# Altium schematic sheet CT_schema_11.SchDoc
size 210 x 185 mm
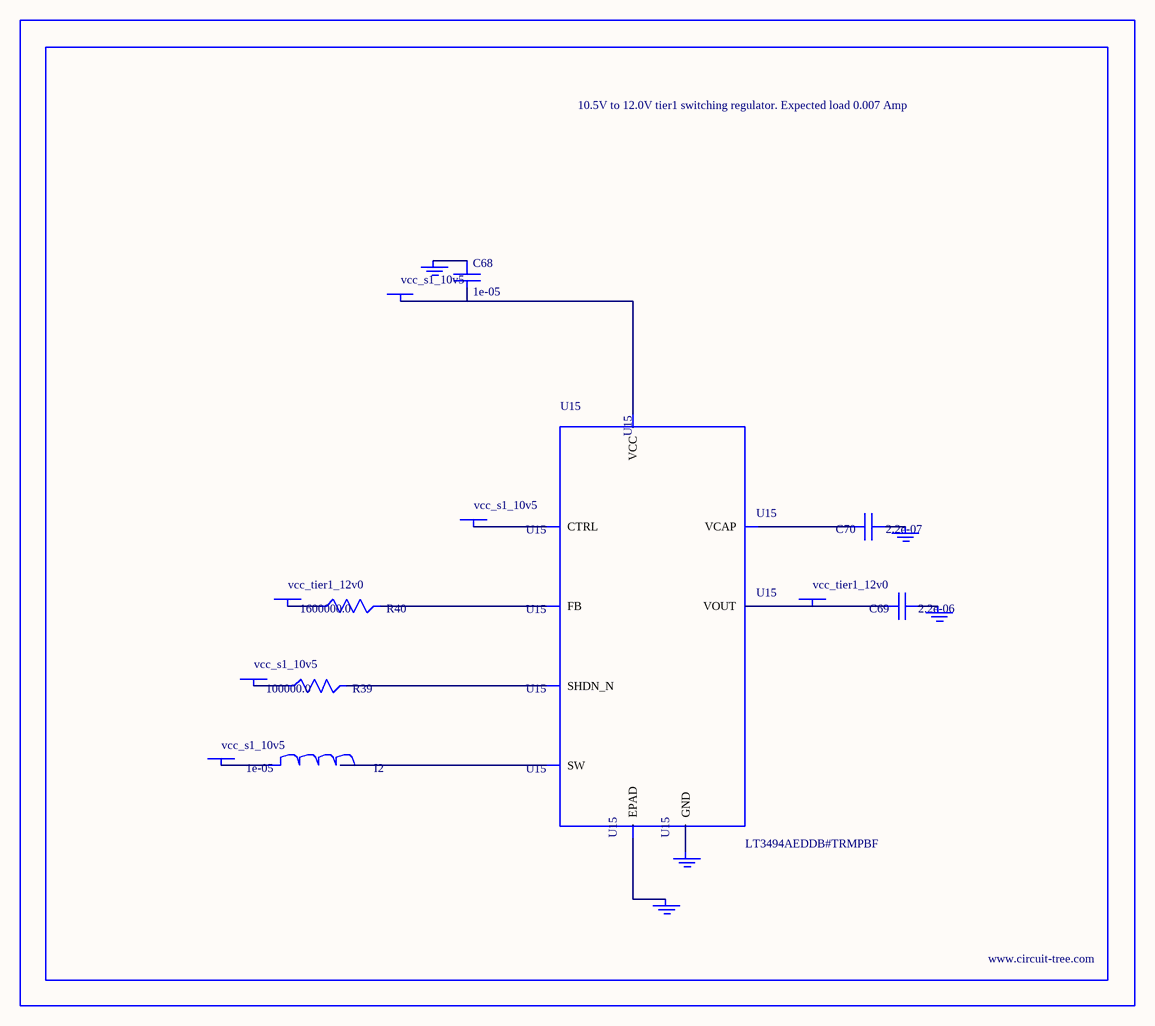
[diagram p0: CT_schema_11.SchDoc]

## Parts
BORDER10  (no value)
C68  1e-05  [C1210]
C69  2.2e-06  [C0603]
C70  2.2e-07  [C0603]
GND_INSTANCE_10_0  (no value)
GND_INSTANCE_10_1  (no value)
GND_INSTANCE_10_2  (no value)
GND_INSTANCE_10_3  (no value)
GND_INSTANCE_10_4  (no value)
I2  1e-05  [L1210]
POWER_INSTANCE_10_0  vcc_s1_10v5
POWER_INSTANCE_10_1  vcc_s1_10v5
POWER_INSTANCE_10_2  vcc_s1_10v5
POWER_INSTANCE_10_3  vcc_s1_10v5
POWER_INSTANCE_10_4  vcc_tier1_12v0
POWER_INSTANCE_10_5  vcc_tier1_12v0
R39  100000.0  [R0603]
R40  1600000.0  [R0603]
U15  LT3494AEDDB#TRMPBF  [DFN-8_DDB]

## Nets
NetC68_1: C68.1 GND_INSTANCE_10_0.0(GND)
NetC68_2: C68.2 POWER_INSTANCE_10_1.0(PWR) U15.3(VCC)
NetC69_1: C69.1 GND_INSTANCE_10_1.0(GND)
NetC69_2: C69.2 POWER_INSTANCE_10_5.0(PWR) U15.7(VOUT)
NetC70_1: C70.1 GND_INSTANCE_10_2.0(GND)
NetC70_2: C70.2 U15.8(VCAP)
NetGND_INSTANCE_10_3_0: GND_INSTANCE_10_3.0(GND) U15.9(EPAD)
NetGND_INSTANCE_10_4_0: GND_INSTANCE_10_4.0(GND) U15.2(GND)
NetI2_1: I2.1 POWER_INSTANCE_10_0.0(PWR)
NetI2_2: I2.2 U15.1(SW)
NetPOWER_INSTANCE_10_2_0: POWER_INSTANCE_10_2.0(PWR) U15.4(CTRL)
NetPOWER_INSTANCE_10_3_0: POWER_INSTANCE_10_3.0(PWR) R39.1
NetPOWER_INSTANCE_10_4_0: POWER_INSTANCE_10_4.0(PWR) R40.1
NetR39_2: R39.2 U15.5(SHDN_N)
NetR40_2: R40.2 U15.6(FB)

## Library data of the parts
BORDER10 = BORDER_PAGE10
C68 = C1210C106K5PACTU
C69 = GRM188R61H225KE1115D
C70 = C0603C224K3RAC
GND_INSTANCE_10_0-GND_INSTANCE_10_4 = GND
I2 = CBC3225T100MR
POWER_INSTANCE_10_0-POWER_INSTANCE_10_5 = PWR
R39 = RC0603JR-07100KL
R40 = RC0603JR-071M6L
